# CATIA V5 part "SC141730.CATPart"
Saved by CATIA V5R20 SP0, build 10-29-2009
Part number: SC141730
Revision: ANY
Definition: UNKNOWN
Nomenclature: SC141730
Source: Unknown
Bounding box of the stored display mesh (mm): x -5.11 to 8.803, y 0 to 17, z -30 to 0
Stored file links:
  C:\Users\Utente\Desktop\IO LAVORO\3D X SITO CF\CUMSA\3D files CG\CG 603035\SC141730.CATPart
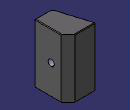
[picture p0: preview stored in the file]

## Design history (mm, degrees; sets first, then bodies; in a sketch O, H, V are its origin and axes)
Body1 "Chaflán2" (main body)
  Solid1: solid without history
